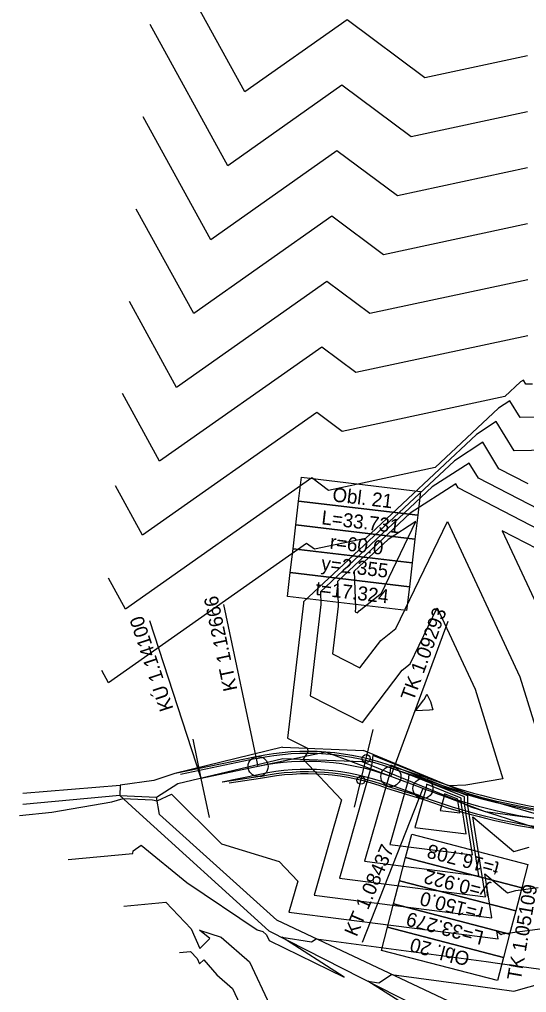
# Model space of a CAD drawing. Extents: x -549394 to -546608, y -1037055 to -1033629.
# Drawn here: x -548463.7 to -548336.9, y -1035543.3 to -1035300.1 of the extents above; entities that cross this region are included whole.
import ezdxf

# ---------------------------------------------------------------- set-up
doc = ezdxf.new("R2010")
doc.units = 0
for name, color, linetype in [('hlavni_vrst', 7, 'Continuous'), ('hrana_L', 7, 'Continuous'), ('norm_vrst', 7, 'Continuous'), ('POLYGONY_SITUACE_PO', 7, 'Continuous'), ('u_sirka_1_0m', 7, 'Continuous'), ('x_navrh_C1', 7, 'Continuous'), ('x_osa_C1', 7, 'Continuous'), ('x_popis_oblouky_C1', 7, 'Continuous'), ('x_popis_pricne_rezy_C1', 7, 'Continuous')]:
    doc.layers.add(name, color=color, linetype=linetype)

msp = doc.modelspace()

# ---------------------------------------------------------------- linework, layer by layer
at = {"layer": 'hlavni_vrst'}
for p, q in [((-548407.38, -1035318.19), (-548429.29, -1035278.27)), ((-548381.81, -1035300.17), (-548407.38, -1035318.19)), ((-548362.33, -1035314.7), (-548381.81, -1035300.17)), ((-548336.7, -1035309.2), (-548362.33, -1035314.7)), ((-548336.63, -1035379.11), (-548379.57, -1035388.33)), ((-548388.12, -1035381.95), (-548428.65, -1035410.51)), ((-548379.57, -1035388.33), (-548388.12, -1035381.95)), ((-548428.65, -1035410.51), (-548437.94, -1035393.59)), ((-548351.25, -1035410.95), (-548360.49, -1035416.91)), ((-548348.93, -1035414.74), (-548351.25, -1035410.95)), ((-548330.45, -1035424.34), (-548348.93, -1035414.74)), ((-548360.49, -1035416.91), (-548388.44, -1035443.11)), ((-548388.44, -1035443.11), (-548388.33, -1035446.34)), ((-548388.33, -1035446.34), (-548391.06, -1035469.16)), ((-548366.02, -1035461.13), (-548359.26, -1035447.11)), ((-548359.26, -1035447.11), (-548349.79, -1035467.47)), ((-548377.98, -1035475.8), (-548368.01, -1035462.7)), ((-548368.01, -1035462.7), (-548366.02, -1035461.13)), ((-548349.79, -1035467.47), (-548342.87, -1035489.84)), ((-548391.06, -1035469.16), (-548377.98, -1035475.8)), ((-548375.38, -1035484.01), (-548375.68, -1035486.56)), ((-548356.35, -1035491.63), (-548375.38, -1035484.01)), ((-548375.68, -1035486.56), (-548383.73, -1035514.73)), ((-548352.09, -1035491.46), (-548356.35, -1035491.63)), ((-548342.87, -1035489.84), (-548352.09, -1035491.46)), ((-548350.36, -1035499.41), (-548340.11, -1035508.02)), ((-548347.23, -1035519.39), (-548350.36, -1035499.41)), ((-548340.11, -1035508.02), (-548336.27, -1035506.94)), ((-548383.73, -1035514.73), (-548347.23, -1035519.39)), ((-548423.7, -1035533.31), (-548420.92, -1035533.06)), ((-548420.92, -1035533.06), (-548419.25, -1035534.82)), ((-548419.25, -1035534.82), (-548418.68, -1035536.12)), ((-548418.68, -1035536.12), (-548417.64, -1035535.08)), ((-548417.64, -1035535.08), (-548414.39, -1035538.86)), ((-548414.39, -1035538.86), (-548410.46, -1035542.31)), ((-548410.46, -1035542.31), (-548402.83, -1035558.47))]:
    msp.add_line(p, q, dxfattribs=at)
at = {"layer": 'hrana_L'}
for p, q in [((-548397.94, -1035481.98), (-548424.88, -1035488.54)), ((-548397.94, -1035481.98), (-548377.67, -1035482.78)), ((-548424.09, -1035491.03), (-548397.82, -1035484.75)), ((-548397.82, -1035484.75), (-548378.09, -1035485.58)), ((-548350.91, -1035493.89), (-548377.67, -1035482.78)), ((-548378.09, -1035485.58), (-548354.63, -1035495.14)), ((-548424.88, -1035488.54), (-548430.1, -1035490.31)), ((-548462.87, -1035493.45), (-548438.55, -1035491.49)), ((-548438.55, -1035491.49), (-548438.59, -1035494.02)), ((-548430.1, -1035490.31), (-548438.55, -1035491.49)), ((-548429.42, -1035494.49), (-548424.09, -1035491.03)), ((-548438.59, -1035494.02), (-548462.82, -1035496.27)), ((-548438.59, -1035494.02), (-548429.42, -1035494.49)), ((-548434.64, -1035497.68), (-548438.59, -1035494.02)), ((-548428.68, -1035498.83), (-548429.42, -1035494.49)), ((-548333.62, -1035498.99), (-548350.91, -1035493.89)), ((-548354.63, -1035495.14), (-548350.9, -1035496.85)), ((-548350.9, -1035496.85), (-548334.77, -1035502.05)), ((-548434.64, -1035497.68), (-548401.33, -1035527.85)), ((-548428.68, -1035498.83), (-548399.35, -1035525.24)), ((-548355.05, -1035546.14), (-548399.35, -1035525.24)), ((-548401.33, -1035527.85), (-548364.53, -1035546.59))]:
    msp.add_line(p, q, dxfattribs=at)
at = {"layer": 'norm_vrst'}
for p, q in [((-548411.64, -1035336.65), (-548431.02, -1035301.34)), ((-548383.07, -1035316.52), (-548411.64, -1035336.65)), ((-548365.77, -1035329.43), (-548383.07, -1035316.52)), ((-548336.69, -1035323.19), (-548365.77, -1035329.43)), ((-548415.89, -1035355.12), (-548432.75, -1035324.4)), ((-548384.33, -1035332.88), (-548415.89, -1035355.12)), ((-548369.22, -1035344.15), (-548384.33, -1035332.88)), ((-548336.67, -1035337.17), (-548369.22, -1035344.15)), ((-548420.14, -1035373.58), (-548434.48, -1035347.46)), ((-548385.59, -1035349.23), (-548420.14, -1035373.58)), ((-548372.67, -1035358.88), (-548385.59, -1035349.23)), ((-548336.66, -1035351.15), (-548372.67, -1035358.88)), ((-548386.85, -1035365.59), (-548424.4, -1035392.05)), ((-548376.12, -1035373.6), (-548386.85, -1035365.59)), ((-548336.64, -1035365.13), (-548376.12, -1035373.6)), ((-548424.4, -1035392.05), (-548436.21, -1035370.53)), ((-548338.44, -1035390.65), (-548342.37, -1035394.33)), ((-548337.73, -1035390.19), (-548338.44, -1035390.65)), ((-548337.1, -1035391.23), (-548337.73, -1035390.19)), ((-548335.42, -1035391.2), (-548337.1, -1035391.23)), ((-548342.37, -1035394.33), (-548383.02, -1035403.05)), ((-548343.95, -1035397.21), (-548359.78, -1035412.05)), ((-548341.11, -1035395.38), (-548343.95, -1035397.21)), ((-548338.56, -1035399.56), (-548341.11, -1035395.38)), ((-548389.38, -1035398.3), (-548432.9, -1035428.98)), ((-548383.02, -1035403.05), (-548389.38, -1035398.3)), ((-548331.8, -1035399.45), (-548338.56, -1035399.56)), ((-548344.49, -1035400.57), (-548349.46, -1035403.78)), ((-548340.02, -1035407.89), (-548344.49, -1035400.57)), ((-548349.46, -1035403.78), (-548377.2, -1035429.77)), ((-548347.87, -1035405.76), (-548354.98, -1035410.35)), ((-548343.84, -1035412.35), (-548347.87, -1035405.76)), ((-548328.18, -1035407.69), (-548340.02, -1035407.89)), ((-548354.98, -1035410.35), (-548392.67, -1035445.67)), ((-548359.78, -1035412.05), (-548386.46, -1035417.78)), ((-548336.56, -1035416.13), (-548343.84, -1035412.35)), ((-548432.9, -1035428.98), (-548439.67, -1035416.65)), ((-548390.64, -1035414.66), (-548437.15, -1035447.44)), ((-548386.46, -1035417.78), (-548390.64, -1035414.66)), ((-548354.63, -1035416.14), (-548366, -1035423.48)), ((-548354.03, -1035417.12), (-548354.63, -1035416.14)), ((-548324.33, -1035432.55), (-548354.03, -1035417.12)), ((-548366, -1035423.48), (-548384.22, -1035440.55)), ((-548373.19, -1035443.45), (-548364.58, -1035425.57)), ((-548364.58, -1035425.57), (-548371.51, -1035430.05)), ((-548369.61, -1035452.29), (-548356.71, -1035425.52)), ((-548356.71, -1035425.52), (-548338.61, -1035464.39)), ((-548318.22, -1035440.75), (-548342.99, -1035427.89)), ((-548342.99, -1035427.89), (-548327.44, -1035461.3)), ((-548391.9, -1035431.02), (-548441.41, -1035465.9)), ((-548389.91, -1035432.5), (-548391.9, -1035431.02)), ((-548377.2, -1035429.77), (-548389.91, -1035432.5)), ((-548371.51, -1035430.05), (-548379.99, -1035437.99)), ((-548379.99, -1035437.99), (-548379.66, -1035447.15)), ((-548437.15, -1035447.44), (-548441.4, -1035439.71)), ((-548384.22, -1035440.55), (-548383.99, -1035446.75)), ((-548378.79, -1035447.86), (-548373.19, -1035443.45)), ((-548392.67, -1035445.67), (-548392.66, -1035445.94)), ((-548392.66, -1035445.94), (-548396.7, -1035479.67)), ((-548383.99, -1035446.75), (-548385.42, -1035458.65)), ((-548379.66, -1035447.15), (-548379.78, -1035448.14)), ((-548379.78, -1035448.14), (-548379.21, -1035448.42)), ((-548379.21, -1035448.42), (-548378.79, -1035447.86)), ((-548373.4, -1035455.28), (-548369.61, -1035452.29)), ((-548378.6, -1035462.11), (-548373.4, -1035455.28)), ((-548385.42, -1035458.65), (-548378.6, -1035462.11)), ((-548441.41, -1035465.9), (-548443.12, -1035462.78)), ((-548338.61, -1035464.39), (-548329.83, -1035492.8)), ((-548364.72, -1035472.88), (-548362.62, -1035470.12)), ((-548362.62, -1035470.12), (-548362.44, -1035469.98)), ((-548362.44, -1035469.98), (-548361.82, -1035468.7)), ((-548361.82, -1035468.7), (-548360.96, -1035470.55)), ((-548360.33, -1035472.59), (-548361.17, -1035472.73)), ((-548360.96, -1035470.55), (-548360.33, -1035472.59)), ((-548361.17, -1035472.73), (-548364.72, -1035472.88)), ((-548396.7, -1035479.67), (-548391.66, -1035482.23)), ((-548391.66, -1035482.23), (-548391.61, -1035483.13)), ((-548391.61, -1035483.13), (-548392.81, -1035484.96)), ((-548392.81, -1035484.96), (-548383.21, -1035495.14)), ((-548370.89, -1035486.42), (-548371.12, -1035488.42)), ((-548351.63, -1035494.13), (-548370.89, -1035486.42)), ((-548371.12, -1035488.42), (-548377.43, -1035510.49)), ((-548366.4, -1035488.83), (-548366.56, -1035490.28)), ((-548352.46, -1035494.41), (-548366.4, -1035488.83)), ((-548366.56, -1035490.28), (-548371.13, -1035506.25)), ((-548361.91, -1035491.24), (-548362.01, -1035492.13)), ((-548353.29, -1035494.69), (-548361.91, -1035491.24)), ((-548429.27, -1035495.38), (-548425.65, -1035493.68)), ((-548425.65, -1035493.68), (-548413.16, -1035506.15)), ((-548362.01, -1035492.13), (-548364.83, -1035502.01)), ((-548357.45, -1035493.99), (-548358.54, -1035497.77)), ((-548357.41, -1035493.65), (-548357.45, -1035493.99)), ((-548354.12, -1035494.97), (-548357.41, -1035493.65)), ((-548352.43, -1035496.15), (-548352.46, -1035494.41)), ((-548351.59, -1035496.53), (-548351.63, -1035494.13)), ((-548455.6, -1035498.21), (-548440.56, -1035495.63)), ((-548440.56, -1035495.63), (-548437.77, -1035494.78)), ((-548437.77, -1035494.78), (-548430.46, -1035495.13)), ((-548430.46, -1035495.13), (-548429.27, -1035495.38)), ((-548383.21, -1035495.14), (-548390.03, -1035518.97)), ((-548354.11, -1035495.38), (-548354.12, -1035494.97)), ((-548353.64, -1035498.39), (-548354.11, -1035495.38)), ((-548353.27, -1035495.76), (-548353.29, -1035494.69)), ((-548352.03, -1035503.64), (-548353.27, -1035495.76)), ((-548350.43, -1035508.89), (-548352.43, -1035496.15)), ((-548348.83, -1035514.14), (-548351.59, -1035496.53)), ((-548463.69, -1035499.07), (-548455.6, -1035498.21)), ((-548358.54, -1035497.77), (-548353.64, -1035498.39)), ((-548364.83, -1035502.01), (-548352.03, -1035503.64)), ((-548435.23, -1035507.85), (-548433.28, -1035506.45)), ((-548433.28, -1035506.45), (-548421.87, -1035515.8)), ((-548413.16, -1035506.15), (-548398.79, -1035510.52)), ((-548371.13, -1035506.25), (-548350.43, -1035508.89)), ((-548451.5, -1035510.04), (-548435.39, -1035508.57)), ((-548435.39, -1035508.57), (-548435.23, -1035507.85)), ((-548398.79, -1035510.52), (-548394.12, -1035515.48)), ((-548377.43, -1035510.49), (-548348.83, -1035514.14)), ((-548347.35, -1035513.66), (-548341.71, -1035518.39)), ((-548345.62, -1035524.64), (-548347.35, -1035513.66)), ((-548421.87, -1035515.8), (-548404.25, -1035527.62)), ((-548394.12, -1035515.48), (-548396.33, -1035523.21)), ((-548341.71, -1035518.39), (-548339.6, -1035517.79)), ((-548339.6, -1035517.79), (-548334.06, -1035517.01)), ((-548437.6, -1035521.68), (-548427.12, -1035520.72)), ((-548427.12, -1035520.72), (-548420.8, -1035527.37)), ((-548390.03, -1035518.97), (-548345.62, -1035524.64)), ((-548396.33, -1035523.21), (-548344.02, -1035529.89)), ((-548420.8, -1035527.37), (-548418.64, -1035532.3)), ((-548418.66, -1035527.72), (-548413.23, -1035529.43)), ((-548416.14, -1035529.79), (-548418.66, -1035527.72)), ((-548404.25, -1035527.62), (-548402.88, -1035528.06)), ((-548402.88, -1035528.06), (-548401.97, -1035528.86)), ((-548344.33, -1035527.91), (-548343.32, -1035528.76)), ((-548344.02, -1035529.89), (-548344.33, -1035527.91)), ((-548342.94, -1035528.65), (-548333.58, -1035527.33)), ((-548418.64, -1035532.3), (-548416.14, -1035529.79)), ((-548413.23, -1035529.43), (-548406.21, -1035535.58)), ((-548401.97, -1035528.86), (-548401.3, -1035530.27)), ((-548401.3, -1035530.27), (-548382.51, -1035539.45)), ((-548382.51, -1035539.45), (-548398.1, -1035529.49)), ((-548398.1, -1035529.49), (-548390.65, -1035530.58)), ((-548390.65, -1035530.58), (-548389.55, -1035529.86)), ((-548389.55, -1035529.86), (-548347.07, -1035535.55)), ((-548343.32, -1035528.76), (-548342.94, -1035528.65)), ((-548406.21, -1035535.58), (-548401.1, -1035546.42)), ((-548347.07, -1035535.55), (-548344.2, -1035535.97)), ((-548344.2, -1035535.97), (-548333.38, -1035537.46)), ((-548368.87, -1035545.38), (-548376.58, -1035540.45)), ((-548376.58, -1035540.45), (-548373.9, -1035540.84)), ((-548373.9, -1035540.84), (-548370.7, -1035538.76)), ((-548370.7, -1035538.76), (-548351.43, -1035541.34)), ((-548340.1, -1035542.96), (-548332.42, -1035540.76)), ((-548351.43, -1035541.34), (-548344.88, -1035542.3)), ((-548344.88, -1035542.3), (-548340.1, -1035542.96))]:
    msp.add_line(p, q, dxfattribs=at)
at = {"layer": 'POLYGONY_SITUACE_PO'}
for centre in [(-548404.04, -1035486.79), (-548370.85, -1035489.3), (-548362.83, -1035492.29)]:
    msp.add_circle(centre, 2.5, dxfattribs=at)
at = {"layer": 'u_sirka_1_0m'}
for centre in [(-548377.01, -1035484.8), (-548378.34, -1035490.24)]:
    msp.add_circle(centre, 1, dxfattribs=at)
at = {"layer": 'x_navrh_C1'}
for p, q in [((-548404.45, -1035484.83), (-548423.47, -1035488.8)), ((-548361.85, -1035489.62), (-548369.99, -1035486.95)), ((-548403.63, -1035488.75), (-548413.04, -1035490.71)), ((-548403.51, -1035489.33), (-548412.97, -1035490.72)), ((-548362.13, -1035490.41), (-548370.15, -1035487.43)), ((-548362.01, -1035490.09), (-548370.15, -1035487.43)), ((-548403.43, -1035489.83), (-548411.29, -1035490.98)), ((-548371.76, -1035491.74), (-548362.17, -1035494.66)), ((-548363.53, -1035494.16), (-548371.55, -1035491.17)), ((-548371.92, -1035492.21), (-548362.33, -1035495.13))]:
    msp.add_line(p, q, dxfattribs=at)
msp.add_lwpolyline([(-548404.55, -1035484.34), (-548424.78, -1035488.56)], dxfattribs=at)
for centre, radius, start, end in [((-548391.79, -1035545.53), 62.5, 69.5785, 101.7797), ((-548391.79, -1035545.53), 62.5, 69.5694, 101.7797), ((-548391.79, -1035545.53), 62, 69.5694, 101.7797), ((-548391.79, -1035545.53), 58, 69.5694, 101.7797), ((-548391.79, -1035545.53), 57.4, 69.5694, 101.7797), ((-548391.79, -1035545.53), 56.9, 69.5541, 101.7948), ((-548310.47, -1035351.72), 147.16, 249.5655, 262.2864), ((-548310.47, -1035351.72), 148, 249.5694, 262.2831), ((-548310.47, -1035351.72), 147.66, 249.5694, 262.2831), ((-548310.47, -1035351.72), 152, 249.5694, 262.2831), ((-548310.47, -1035351.72), 152.5, 250.1175, 262.2831)]:
    msp.add_arc(centre, radius, start, end, dxfattribs=at)
at = {"layer": 'x_osa_C1'}
for points in [[(-548083.39, -1035461.06), (-548191.13, -1035486.15), (-548219.76, -1035492.15), (-548249.9, -1035495.61), (-548275.65, -1035501.47), (-548299.34, -1035504.6), (-548347.17, -1035498.12)], [(-548387.08, -1035483.25), (-548418.26, -1035489.75)], [(-548347.17, -1035498.12), (-548387.08, -1035483.25)]]:
    msp.add_lwpolyline(points, dxfattribs=at)
for centre, radius, start, end in [((-548391.79, -1035545.53), 60, 69.5694, 101.7797), ((-548310.47, -1035351.72), 150, 249.5694, 262.2831)]:
    msp.add_arc(centre, radius, start, end, dxfattribs=at)
at = {"layer": 'x_popis_oblouky_C1'}
for points in [[(-548393.2, -1035414.51), (-548363.41, -1035418.03), (-548364.11, -1035423.99), (-548393.9, -1035420.47)], [(-548393.9, -1035420.47), (-548364.11, -1035423.99), (-548364.82, -1035429.95), (-548394.61, -1035426.42)], [(-548394.61, -1035426.42), (-548364.82, -1035429.95), (-548365.52, -1035435.91), (-548395.31, -1035432.38)], [(-548395.31, -1035432.38), (-548365.52, -1035435.91), (-548366.23, -1035441.87), (-548396.02, -1035438.34)], [(-548396.02, -1035438.34), (-548366.23, -1035441.87), (-548366.93, -1035447.83), (-548396.72, -1035444.3)], [(-548338.13, -1035517.1), (-548367.16, -1035509.53), (-548365.65, -1035503.73), (-548336.62, -1035511.29)], [(-548339.65, -1035522.9), (-548368.68, -1035515.34), (-548367.16, -1035509.53), (-548338.13, -1035517.1)], [(-548341.16, -1035528.71), (-548370.19, -1035521.14), (-548368.68, -1035515.34), (-548339.65, -1035522.9)], [(-548342.67, -1035534.52), (-548371.7, -1035526.95), (-548370.19, -1035521.14), (-548341.16, -1035528.71)], [(-548344.18, -1035540.32), (-548373.21, -1035532.76), (-548371.7, -1035526.95), (-548342.67, -1035534.52)]]:
    msp.add_lwpolyline(points, close=True, dxfattribs=at)
for points in [[(-548404.04, -1035486.79), (-548412.63, -1035446.32)], [(-548418.28, -1035489.75), (-548431.07, -1035450.41)], [(-548370.85, -1035489.3), (-548356.57, -1035450.47)], [(-548362.83, -1035492.29), (-548378.04, -1035530.77)]]:
    msp.add_lwpolyline(points, dxfattribs=at)
at = {"layer": 'x_popis_pricne_rezy_C1'}
for points in [[(-548379.97, -1035496.94), (-548377.6, -1035487.23), (-548375.24, -1035477.51)], [(-548416.21, -1035499.54), (-548418.26, -1035489.75), (-548420.3, -1035479.96)]]:
    msp.add_lwpolyline(points, dxfattribs=at)

# ---------------------------------------------------------------- texts
at = {"layer": 'x_popis_oblouky_C1'}
for s, rotation, p in [('Obl. 21', 353.2713, (-548385.6, -1035420.5)), ('L=33.731', 353.2713, (-548388.33, -1035426.22)), ('r=60.0', 353.2713, (-548386.24, -1035432.33)), ('y=2.355', 353.2713, (-548388.4, -1035437.67)), ('t=17.324', 353.2713, (-548389.84, -1035443.9)), ('KT 1.12666', 101.9782, (-548409.19, -1035467.57)), ('TK 1.09293', 69.7788, (-548365.22, -1035470.64)), ('KÚ 1.14100', 108.3258, (-548425.15, -1035472.33)), ('KT 1.08437', 67.059, (-548379.41, -1035529.52)), ('t=16.708', 165.4151, (-548343.49, -1035510.75)), ('y=0.922', 165.4151, (-548345.77, -1035516.72)), ('TK 1.05109', 80.0766, (-548338.39, -1035540.41)), ('r=150.0', 165.4151, (-548347.51, -1035522.01)), ('L=33.279', 165.4151, (-548347.4, -1035528.06)), ('Obl. 20', 165.4151, (-548350.89, -1035533.35))]:
    msp.add_text(s, height=3.5, rotation=rotation, dxfattribs=at).set_placement(p)

doc.saveas('drawing.dxf')
